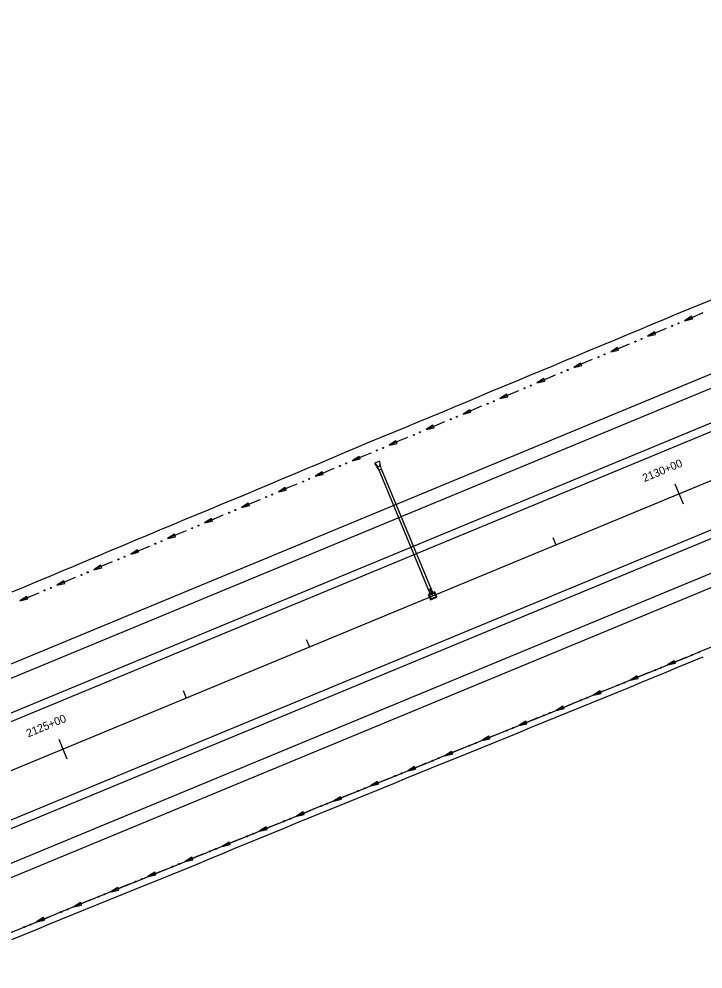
# Model space of a CAD drawing. Extents: x 1611108 to 1749517, y 619561 to 797725.
# Drawn here: x 1718515 to 1719028, y 766660 to 767372 of the extents above; entities that cross this region are included whole.
import ezdxf

# ---------------------------------------------------------------- set-up
doc = ezdxf.new("R2010")
doc.units = 0
for name, color, linetype in [('R_Ditch', 7, 'Continuous'), ('R_Drainage', 7, 'Continuous'), ('R_Horz Alg', 7, 'Continuous'), ('R_Horz Alg Stationing', 7, 'Continuous'), ('R_Proposed Const Limits', 7, 'Continuous'), ('R_Proposed Road', 7, 'Continuous')]:
    doc.layers.add(name, color=color, linetype=linetype)

msp = doc.modelspace()

# ---------------------------------------------------------------- linework, layer by layer
at = {"layer": 'R_Ditch'}
for p, q in [((1719018.9, 767149.28), (1719013.78, 767145.97)), ((1719013.78, 767145.97), (1719019.72, 767147.33)), ((1719019.72, 767147.33), (1719018.9, 767149.28)), ((1718991.22, 767137.62), (1718986.1, 767134.31)), ((1718986.1, 767134.31), (1718992.04, 767135.67)), ((1718992.04, 767135.67), (1718991.22, 767137.62)), ((1718963.53, 767125.95), (1718958.42, 767122.65)), ((1718964.36, 767124), (1718963.53, 767125.95)), ((1718958.42, 767122.65), (1718964.36, 767124)), ((1718935.85, 767114.29), (1718930.73, 767110.99)), ((1718930.73, 767110.99), (1718936.67, 767112.34)), ((1718936.67, 767112.34), (1718935.85, 767114.29)), ((1718908.17, 767102.63), (1718903.05, 767099.33)), ((1718903.05, 767099.33), (1718908.99, 767100.68)), ((1718908.99, 767100.68), (1718908.17, 767102.63)), ((1718880.49, 767090.97), (1718875.37, 767087.67)), ((1718881.31, 767089.02), (1718880.49, 767090.97)), ((1718875.37, 767087.67), (1718881.31, 767089.02)), ((1718852.81, 767079.31), (1718847.69, 767076)), ((1718847.69, 767076), (1718853.63, 767077.36)), ((1718853.63, 767077.36), (1718852.81, 767079.31)), ((1718825.12, 767067.65), (1718820.01, 767064.34)), ((1718820.01, 767064.34), (1718825.95, 767065.7)), ((1718825.95, 767065.7), (1718825.12, 767067.65)), ((1718797.44, 767055.99), (1718792.32, 767052.68)), ((1718798.26, 767054.04), (1718797.44, 767055.99)), ((1718792.32, 767052.68), (1718798.26, 767054.04)), ((1718769.76, 767044.33), (1718764.64, 767041.02)), ((1718764.64, 767041.02), (1718770.58, 767042.38)), ((1718770.58, 767042.38), (1718769.76, 767044.33)), ((1718742.08, 767032.66), (1718736.96, 767029.36)), ((1718736.96, 767029.36), (1718742.9, 767030.71)), ((1718742.9, 767030.71), (1718742.08, 767032.66)), ((1718714.4, 767021), (1718709.28, 767017.7)), ((1718709.28, 767017.7), (1718715.22, 767019.05)), ((1718715.22, 767019.05), (1718714.4, 767021)), ((1718686.71, 767009.34), (1718681.6, 767006.04)), ((1718681.6, 767006.04), (1718687.54, 767007.39)), ((1718687.54, 767007.39), (1718686.71, 767009.34)), ((1718659.03, 766997.68), (1718653.91, 766994.38)), ((1718659.85, 766995.73), (1718659.03, 766997.68)), ((1718653.91, 766994.38), (1718659.85, 766995.73)), ((1718631.35, 766986.02), (1718626.23, 766982.71)), ((1718626.23, 766982.71), (1718632.17, 766984.07)), ((1718632.17, 766984.07), (1718631.35, 766986.02)), ((1718603.67, 766974.36), (1718598.55, 766971.05)), ((1718598.55, 766971.05), (1718604.49, 766972.41)), ((1718604.49, 766972.41), (1718603.67, 766974.36)), ((1718575.99, 766962.7), (1718570.87, 766959.39)), ((1718576.81, 766960.75), (1718575.99, 766962.7)), ((1718570.87, 766959.39), (1718576.81, 766960.75)), ((1718548.3, 766951.03), (1718543.19, 766947.73)), ((1718543.19, 766947.73), (1718549.13, 766949.08)), ((1718549.13, 766949.08), (1718548.3, 766951.03)), ((1718520.62, 766939.37), (1718515.5, 766936.07)), ((1718515.5, 766936.07), (1718521.44, 766937.42)), ((1718521.44, 766937.42), (1718520.62, 766939.37)), ((1719006.09, 766891.19), (1719000.93, 766887.95)), ((1719006.88, 766889.23), (1719006.09, 766891.19)), ((1719000.93, 766887.95), (1719006.88, 766889.23)), ((1718978.27, 766879.86), (1718973.11, 766876.62)), ((1718973.11, 766876.62), (1718979.06, 766877.9)), ((1718979.06, 766877.9), (1718978.27, 766879.86)), ((1718950.45, 766868.53), (1718945.29, 766865.29)), ((1718945.29, 766865.29), (1718951.24, 766866.57)), ((1718951.24, 766866.57), (1718950.45, 766868.53)), ((1718922.63, 766857.2), (1718917.47, 766853.96)), ((1718917.47, 766853.96), (1718923.42, 766855.24)), ((1718923.42, 766855.24), (1718922.63, 766857.2)), ((1718894.81, 766845.88), (1718889.65, 766842.63)), ((1718889.65, 766842.63), (1718895.6, 766843.92)), ((1718895.6, 766843.92), (1718894.81, 766845.88)), ((1718866.99, 766834.55), (1718861.83, 766831.3)), ((1718867.78, 766832.59), (1718866.99, 766834.55)), ((1718861.83, 766831.3), (1718867.78, 766832.59)), ((1718839.17, 766823.22), (1718834.01, 766819.98)), ((1718834.01, 766819.98), (1718839.96, 766821.26)), ((1718839.96, 766821.26), (1718839.17, 766823.22)), ((1718811.35, 766811.89), (1718806.19, 766808.65)), ((1718806.19, 766808.65), (1718812.14, 766809.93)), ((1718812.14, 766809.93), (1718811.35, 766811.89)), ((1718783.53, 766800.56), (1718778.37, 766797.32)), ((1718778.37, 766797.32), (1718784.33, 766798.6)), ((1718784.33, 766798.6), (1718783.53, 766800.56)), ((1718755.71, 766789.23), (1718750.55, 766785.99)), ((1718750.55, 766785.99), (1718756.51, 766787.27)), ((1718756.51, 766787.27), (1718755.71, 766789.23)), ((1718727.89, 766777.91), (1718722.73, 766774.66)), ((1718728.68, 766775.95), (1718727.89, 766777.91)), ((1718722.73, 766774.66), (1718728.68, 766775.95)), ((1718700.07, 766766.58), (1718694.91, 766763.33)), ((1718694.91, 766763.33), (1718700.87, 766764.62)), ((1718700.87, 766764.62), (1718700.07, 766766.58)), ((1718672.25, 766755.25), (1718667.09, 766752.01)), ((1718667.09, 766752.01), (1718673.05, 766753.29)), ((1718673.05, 766753.29), (1718672.25, 766755.25)), ((1718644.43, 766743.92), (1718639.27, 766740.68)), ((1718639.27, 766740.68), (1718645.23, 766741.96)), ((1718645.23, 766741.96), (1718644.43, 766743.92)), ((1718616.61, 766732.59), (1718611.45, 766729.35)), ((1718611.45, 766729.35), (1718617.41, 766730.63)), ((1718617.41, 766730.63), (1718616.61, 766732.59)), ((1718588.79, 766721.26), (1718583.63, 766718.02)), ((1718589.59, 766719.3), (1718588.79, 766721.26)), ((1718583.63, 766718.02), (1718589.59, 766719.3)), ((1718560.97, 766709.94), (1718555.81, 766706.69)), ((1718555.81, 766706.69), (1718561.77, 766707.98)), ((1718561.77, 766707.98), (1718560.97, 766709.94)), ((1718533.15, 766698.61), (1718527.99, 766695.36)), ((1718533.95, 766696.65), (1718533.15, 766698.61)), ((1718527.99, 766695.36), (1718533.95, 766696.65))]:
    msp.add_line(p, q, dxfattribs=at)
for points in [[(1719027.6, 767151.8), (1719019.8, 767148.51), (1719013.78, 767145.97)], [(1718999.92, 767140.14), (1718992.16, 767136.86), (1718986.1, 767134.31)], [(1718999.96, 767140.15), (1718999.92, 767140.14)], [(1718972.24, 767128.47), (1718964.51, 767125.22), (1718958.42, 767122.65)], [(1718972.27, 767128.49), (1718972.24, 767128.47)], [(1718944.56, 767116.81), (1718936.86, 767113.57), (1718930.73, 767110.99)], [(1718944.59, 767116.83), (1718944.56, 767116.81)], [(1718916.88, 767105.15), (1718909.21, 767101.92), (1718903.05, 767099.33)], [(1718916.91, 767105.17), (1718916.88, 767105.15)], [(1718889.19, 767093.49), (1718881.57, 767090.28), (1718875.37, 767087.67)], [(1718889.23, 767093.5), (1718889.19, 767093.49)], [(1718861.51, 767081.83), (1718853.92, 767078.63), (1718847.69, 767076)], [(1718861.55, 767081.84), (1718861.51, 767081.83)], [(1718833.83, 767070.17), (1718826.27, 767066.98), (1718820.01, 767064.34)], [(1718833.86, 767070.18), (1718833.83, 767070.17)], [(1718806.15, 767058.51), (1718798.62, 767055.34), (1718792.32, 767052.68)], [(1718806.18, 767058.52), (1718806.15, 767058.51)], [(1718778.47, 767046.84), (1718770.98, 767043.69), (1718764.64, 767041.02)], [(1718778.5, 767046.86), (1718778.47, 767046.84)], [(1718750.78, 767035.18), (1718743.33, 767032.04), (1718736.96, 767029.36)], [(1718750.82, 767035.2), (1718750.78, 767035.18)], [(1718723.1, 767023.52), (1718715.68, 767020.4), (1718709.28, 767017.7)], [(1718723.14, 767023.54), (1718723.1, 767023.52)], [(1718695.42, 767011.86), (1718688.03, 767008.75), (1718681.6, 767006.04)], [(1718695.45, 767011.87), (1718695.42, 767011.86)], [(1718667.74, 767000.2), (1718660.39, 766997.1), (1718653.91, 766994.38)], [(1718667.77, 767000.21), (1718667.74, 767000.2)], [(1718640.06, 766988.54), (1718632.74, 766985.45), (1718626.23, 766982.71)], [(1718640.09, 766988.55), (1718640.06, 766988.54)], [(1718612.37, 766976.88), (1718605.09, 766973.81), (1718598.55, 766971.05)], [(1718612.41, 766976.89), (1718612.37, 766976.88)], [(1718584.69, 766965.21), (1718577.44, 766962.16), (1718570.87, 766959.39)], [(1718584.73, 766965.23), (1718584.69, 766965.22)], [(1718557.01, 766953.55), (1718549.8, 766950.51), (1718543.19, 766947.73)], [(1718557.04, 766953.57), (1718557.01, 766953.55)], [(1718529.33, 766941.89), (1718522.15, 766938.87), (1718515.5, 766936.07)], [(1718529.36, 766941.91), (1718529.33, 766941.89)], [(1718507.42, 766686.99), (1718516.68, 766690.76), (1718525.94, 766694.53), (1718535.2, 766698.3), (1718544.46, 766702.07), (1718553.73, 766705.84), (1718562.99, 766709.62), (1718572.25, 766713.39), (1718581.51, 766717.16), (1718590.77, 766720.93), (1718600.04, 766724.7), (1718609.3, 766728.47), (1718618.56, 766732.24), (1718627.82, 766736.02), (1718637.08, 766739.79), (1718646.34, 766743.56), (1718655.6, 766747.33), (1718664.87, 766751.1), (1718674.13, 766754.87), (1718683.39, 766758.64), (1718692.65, 766762.42), (1718701.91, 766766.19), (1718711.18, 766769.96), (1718720.44, 766773.73), (1718729.7, 766777.5), (1718738.96, 766781.27), (1718748.22, 766785.04), (1718757.49, 766788.82), (1718766.75, 766792.59), (1718776.01, 766796.36), (1718785.27, 766800.13), (1718794.53, 766803.9), (1718803.79, 766807.67), (1718813.05, 766811.44), (1718822.32, 766815.21), (1718831.58, 766818.99), (1718840.84, 766822.76), (1718850.1, 766826.53), (1718859.36, 766830.3), (1718868.63, 766834.07), (1718877.89, 766837.84), (1718887.15, 766841.61), (1718896.41, 766845.39), (1718905.67, 766849.16), (1718914.93, 766852.93), (1718924.2, 766856.7), (1718933.46, 766860.47), (1718942.72, 766864.24), (1718951.98, 766868.02), (1718961.24, 766871.79), (1718970.51, 766875.56), (1718979.77, 766879.33), (1718989.03, 766883.1), (1718998.29, 766886.87), (1719007.55, 766890.64), (1719016.81, 766894.41), (1719026.08, 766898.19), (1719035.34, 766901.96)], [(1719014.82, 766893.6), (1719007.55, 766890.64), (1719000.93, 766887.95)], [(1719014.86, 766893.62), (1719014.82, 766893.6)], [(1718987, 766882.27), (1718979.77, 766879.33), (1718973.11, 766876.62)], [(1718987.04, 766882.29), (1718987, 766882.27)], [(1718959.18, 766870.95), (1718951.98, 766868.02), (1718945.29, 766865.29)], [(1718959.22, 766870.96), (1718959.18, 766870.95)], [(1718931.36, 766859.62), (1718924.2, 766856.7), (1718917.47, 766853.96)], [(1718931.4, 766859.63), (1718931.36, 766859.62)], [(1718903.54, 766848.29), (1718896.41, 766845.39), (1718889.65, 766842.63)], [(1718903.58, 766848.3), (1718903.54, 766848.29)], [(1718875.72, 766836.96), (1718868.63, 766834.07), (1718861.83, 766831.3)], [(1718875.76, 766836.98), (1718875.72, 766836.96)], [(1718847.9, 766825.63), (1718840.84, 766822.76), (1718834.01, 766819.98)], [(1718847.94, 766825.65), (1718847.9, 766825.63)], [(1718820.08, 766814.3), (1718813.05, 766811.44), (1718806.19, 766808.65)], [(1718820.12, 766814.32), (1718820.08, 766814.3)], [(1718792.26, 766802.98), (1718785.27, 766800.13), (1718778.37, 766797.32)], [(1718792.3, 766802.99), (1718792.26, 766802.98)], [(1718764.44, 766791.65), (1718757.49, 766788.82), (1718750.55, 766785.99)], [(1718764.48, 766791.66), (1718764.44, 766791.65)], [(1718736.62, 766780.32), (1718729.7, 766777.5), (1718722.73, 766774.66)], [(1718736.66, 766780.33), (1718736.62, 766780.32)], [(1718708.8, 766768.99), (1718701.91, 766766.19), (1718694.91, 766763.33)], [(1718708.84, 766769.01), (1718708.8, 766768.99)], [(1718680.98, 766757.66), (1718674.13, 766754.87), (1718667.09, 766752.01)], [(1718681.02, 766757.68), (1718680.98, 766757.66)], [(1718653.16, 766746.33), (1718646.34, 766743.56), (1718639.27, 766740.68)], [(1718653.2, 766746.35), (1718653.16, 766746.33)], [(1718625.34, 766735.01), (1718618.56, 766732.24), (1718611.45, 766729.35)], [(1718625.38, 766735.02), (1718625.34, 766735.01)], [(1718597.52, 766723.68), (1718590.77, 766720.93), (1718583.63, 766718.02)], [(1718597.56, 766723.69), (1718597.52, 766723.68)], [(1718569.7, 766712.35), (1718562.99, 766709.62), (1718555.81, 766706.69)], [(1718569.74, 766712.36), (1718569.7, 766712.35)], [(1718541.88, 766701.02), (1718535.2, 766698.3), (1718527.99, 766695.36)], [(1718541.92, 766701.04), (1718541.88, 766701.02)]]:
    msp.add_lwpolyline(points, dxfattribs=at)
for centre in [(1719004.56, 767142.05), (1719009.18, 767144), (1718981.5, 767132.33), (1718976.88, 767130.39), (1718949.2, 767118.73), (1718953.82, 767120.67), (1718921.52, 767107.07), (1718926.14, 767109.01), (1718898.45, 767097.35), (1718893.84, 767095.41), (1718866.15, 767083.74), (1718870.77, 767085.69), (1718838.47, 767072.08), (1718843.09, 767074.03), (1718815.41, 767062.37), (1718810.79, 767060.42), (1718783.11, 767048.76), (1718787.72, 767050.71), (1718755.43, 767037.1), (1718760.04, 767039.04), (1718732.36, 767027.38), (1718727.74, 767025.44), (1718700.06, 767013.78), (1718704.68, 767015.72), (1718672.38, 767002.12), (1718677, 767004.06), (1718644.7, 766990.45), (1718649.31, 766992.4), (1718617.02, 766978.79), (1718621.63, 766980.74), (1718593.95, 766969.08), (1718589.33, 766967.13), (1718561.65, 766955.47), (1718566.27, 766957.41), (1718533.97, 766943.81), (1718538.59, 766945.75), (1719024.13, 766897.35), (1719019.49, 766895.46), (1718991.67, 766884.14), (1718996.31, 766886.02), (1718963.85, 766872.81), (1718968.49, 766874.7), (1718940.67, 766863.37), (1718936.03, 766861.48), (1718908.21, 766850.15), (1718912.85, 766852.04), (1718885.03, 766840.71), (1718880.39, 766838.82), (1718852.57, 766827.49), (1718857.21, 766829.38), (1718824.75, 766816.17), (1718829.39, 766818.05), (1718796.93, 766804.84), (1718801.57, 766806.73), (1718769.11, 766793.51), (1718773.75, 766795.4), (1718745.93, 766784.07), (1718741.29, 766782.18), (1718713.47, 766770.85), (1718718.11, 766772.74), (1718685.65, 766759.52), (1718690.29, 766761.41), (1718657.83, 766748.2), (1718662.47, 766750.08), (1718630.01, 766736.87), (1718634.65, 766738.76), (1718606.83, 766727.43), (1718602.19, 766725.54), (1718574.37, 766714.21), (1718579.01, 766716.1), (1718546.55, 766702.88), (1718551.19, 766704.77), (1718518.73, 766691.55), (1718523.37, 766693.44)]:
    msp.add_circle(centre, 0.375, dxfattribs=at)
at = {"layer": 'R_Drainage'}
for p, q in [((1718785.15, 767040.83), (1718781.45, 767039.29)), ((1718786.57, 767034.79), (1718785.15, 767040.83)), ((1718785.15, 767040.83), (1718785.4, 767037.9)), ((1718784.72, 767034.02), (1718781.45, 767039.29)), ((1718781.45, 767039.29), (1718783.35, 767037.05)), ((1718786.57, 767034.79), (1718784.72, 767034.02)), ((1718823.37, 766940.71), (1718784.72, 767034.02)), ((1718825.22, 766941.48), (1718786.57, 767034.79))]:
    msp.add_line(p, q, dxfattribs=at)
for points in [[(1718821.58, 766940.69), (1718823.24, 766936.69), (1718828.16, 766938.73), (1718826.5, 766942.73)], [(1718822.45, 766940.33), (1718823.6, 766937.56), (1718827.29, 766939.09), (1718826.14, 766941.86)]]:
    msp.add_lwpolyline(points, close=True, dxfattribs=at)
msp.add_arc((1718784.24, 767037.79), 1.17, 220.02993, 4.97008, dxfattribs=at)
at = {"layer": 'R_Horz Alg'}
msp.add_line((1715964.86, 765755.05), (1723860.62, 769025.58), dxfattribs=at)
at = {"layer": 'R_Horz Alg Stationing'}
for points in [[(1719006.58, 767023.64), (1719012.71, 767008.85)], [(1718914.96, 766983.52), (1718917.26, 766977.98)], [(1718822.57, 766945.25), (1718824.87, 766939.71)], [(1718730.19, 766906.98), (1718732.48, 766901.44)], [(1718637.8, 766868.71), (1718640.09, 766863.17)], [(1718544.64, 766832.29), (1718550.77, 766817.51)]]:
    msp.add_lwpolyline(points, dxfattribs=at)
at = {"layer": 'R_Proposed Const Limits'}
for points in [[(1718509.74, 766942.69), (1718518.95, 766946.58), (1718528.16, 766950.48), (1718537.38, 766954.36), (1718546.6, 766958.22), (1718555.82, 766962.09), (1718565.04, 766965.96), (1718574.27, 766969.83), (1718583.49, 766973.7), (1718592.7, 766977.58), (1718601.94, 766981.42), (1718611.16, 766985.28), (1718620.37, 766989.17), (1718629.59, 766993.06), (1718638.8, 766996.94), (1718648.04, 767000.78), (1718657.29, 767004.58), (1718666.53, 767008.39), (1718675.78, 767012.2), (1718685.03, 767016.01), (1718694.24, 767019.89), (1718703.45, 767023.79), (1718712.66, 767027.68), (1718721.88, 767031.57), (1718731.09, 767035.45), (1718740.31, 767039.34), (1718749.52, 767043.23), (1718758.73, 767047.12), (1718767.94, 767051.01), (1718777.16, 767054.9), (1718786.41, 767058.7), (1718795.66, 767062.5), (1718804.91, 767066.3), (1718814.16, 767070.1), (1718823.41, 767073.9), (1718832.63, 767077.77), (1718841.84, 767081.66), (1718851.05, 767085.54), (1718860.27, 767089.43), (1718869.48, 767093.32), (1718878.71, 767097.18), (1718887.95, 767101.01), (1718897.18, 767104.84), (1718906.42, 767108.67), (1718915.66, 767112.5), (1718924.89, 767116.35), (1718934.11, 767120.2), (1718943.34, 767124.06), (1718952.57, 767127.91), (1718961.8, 767131.76), (1718971.02, 767135.62), (1718980.24, 767139.49), (1718989.46, 767143.36), (1718998.68, 767147.24), (1719007.9, 767151.11), (1719017.15, 767154.91), (1719026.41, 767158.69), (1719035.67, 767162.47)], [(1718509.42, 766682.15), (1718518.67, 766685.96), (1718527.91, 766689.77), (1718537.16, 766693.58), (1718546.4, 766697.4), (1718555.66, 766701.17), (1718564.93, 766704.93), (1718574.19, 766708.69), (1718583.46, 766712.46), (1718592.72, 766716.23), (1718601.99, 766719.99), (1718611.26, 766723.74), (1718620.53, 766727.48), (1718629.8, 766731.23), (1718639.08, 766734.97), (1718648.32, 766738.78), (1718657.57, 766742.59), (1718666.8, 766746.42), (1718676.02, 766750.3), (1718685.24, 766754.18), (1718694.49, 766757.98), (1718703.75, 766761.76), (1718713.02, 766765.52), (1718722.28, 766769.28), (1718731.55, 766773.03), (1718740.81, 766776.81), (1718750.07, 766780.59), (1718759.32, 766784.38), (1718768.58, 766788.15), (1718777.84, 766791.93), (1718787.1, 766795.71), (1718796.36, 766799.49), (1718805.61, 766803.28), (1718814.87, 766807.06), (1718824.14, 766810.81), (1718833.41, 766814.57), (1718842.68, 766818.32), (1718851.95, 766822.08), (1718861.22, 766825.83), (1718870.48, 766829.59), (1718879.74, 766833.38), (1718888.98, 766837.19), (1718898.23, 766840.98), (1718907.5, 766844.75), (1718916.76, 766848.51), (1718926.03, 766852.28), (1718935.29, 766856.05), (1718944.55, 766859.83), (1718953.81, 766863.6), (1718963.07, 766867.38), (1718972.32, 766871.19), (1718981.56, 766875), (1718990.81, 766878.81), (1719000.04, 766882.64), (1719009.28, 766886.46), (1719018.54, 766890.25), (1719027.79, 766894.04)]]:
    msp.add_lwpolyline(points, dxfattribs=at)
at = {"layer": 'R_Proposed Road'}
for p, q in [((1715936.54, 765823.42), (1723832.3, 769093.95)), ((1715940.37, 765814.18), (1723836.12, 769084.71)), ((1715949.55, 765792.01), (1723845.31, 769062.54)), ((1715951.85, 765786.47), (1723847.6, 769056.99)), ((1715977.87, 765723.64), (1723873.63, 768994.17)), ((1715980.17, 765718.1), (1723875.92, 768988.63)), ((1715989.35, 765695.93), (1723885.11, 768966.45)), ((1715993.18, 765686.69), (1723888.93, 768957.22))]:
    msp.add_line(p, q, dxfattribs=at)

# ---------------------------------------------------------------- texts
at = {"layer": 'R_Horz Alg Stationing'}
for s, p in [('2130+00', (1718983.68, 767024.97)), ('2125+00', (1718521.74, 766833.63))]:
    msp.add_text(s, height=6, rotation=22.5, dxfattribs=at).set_placement(p)

doc.saveas('drawing.dxf')
